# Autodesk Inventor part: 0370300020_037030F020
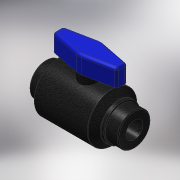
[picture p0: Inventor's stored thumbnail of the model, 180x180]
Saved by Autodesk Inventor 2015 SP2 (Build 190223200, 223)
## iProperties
Created: 2017-06
Part Number: 0370300020_037030F020
Material: PVC-Piping
Description: PLASSON BALL VALVE DN50 FEMALE 2" BSPT
Document SubType Name: Modeling
Designer: KIM
Mass: 1769.62 g
Surface Area: 955.791 cm^2
Volume: 1264.02 cm^3
Density: 1.4 g/cm^3
Appearance: Black Cast
Author: KIM
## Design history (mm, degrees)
derived "03703.ipt"
feature "Solid1::03703.ipt"
tag "TaggingFeature1"
body "Solid1"
other parameters: "d0" = 162, "d3" = 106, "d4" = 29, "d5" = 56.656, "d6" = 56.656, "d7" = 29, "d8" = 75, "d9" = 23.2, "d10" = 82.5, "d11" = 15.0485, "d12" = 135 deg, "d14" = 2.8328, "d24" = 33.9936, "d25" = 68.9, "d27" = 33.9936, "d28" = 16.9968, "d29" = 28.1, "d30" = 0, "d32" = 74.78592, "d33" = 8.4984, "d34" = 2.8328, "Rc_" = 56.656, "A_1" = 53, "A_2" = 97, "H_" = 162, "l_" = 29, "B_" = 75, "E_" = 1, "d31" = 67.9872
